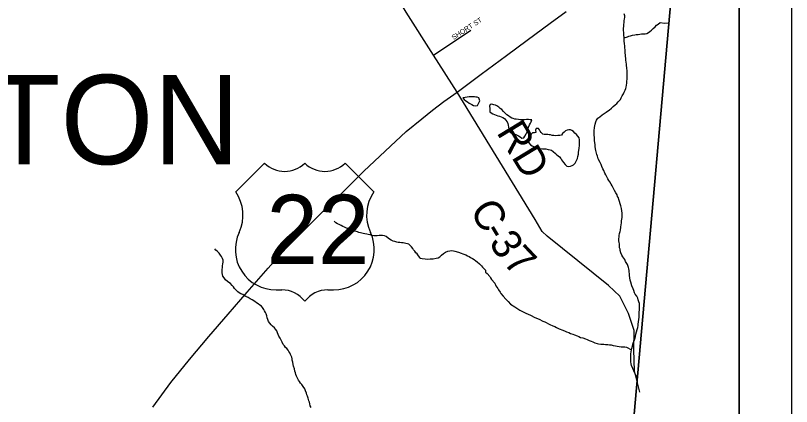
# Model space of a CAD drawing. Extents: x 0.4 to 34.4, y -2.1 to 19.9.
# Drawn here: x 8.419 to 9.9, y 13.092 to 13.838 of the extents above; entities that cross this region are included whole.
import ezdxf

# ---------------------------------------------------------------- set-up
doc = ezdxf.new("R2010")
doc.units = 0
for name, color, linetype in [('GM_X_Adjacent_County', 7, 'Continuous'), ('GM_X_County', 7, 'Continuous'), ('GM_X_County_Road', 7, 'Continuous'), ('GM_X_County_Road_Text', 7, 'Continuous'), ('GM_X_Minor_Lake', 7, 'Continuous'), ('GM_X_Minor_River', 7, 'Continuous'), ('GM_X_Township', 7, 'Continuous'), ('GM_X_Township_Subdivision', 7, 'Continuous'), ('GM_X_Township_Subdivision_Text', 7, 'Continuous'), ('GM_X_Township_Text', 7, 'Continuous'), ('GM_X_US_Route', 7, 'Continuous'), ('GM_X_US_Shield', 7, 'Continuous'), ('SH_Data', 7, 'Continuous')]:
    doc.layers.add(name, color=color, linetype=linetype)

msp = doc.modelspace()

# ---------------------------------------------------------------- linework, layer by layer
at = {"layer": 'GM_X_Adjacent_County'}
for points in [[(9.5074, 12.0357), (9.8001, 12.0357), (9.8001, 15.3423)], [(9.8001, 15.3423), (9.7654, 14.9495), (9.706, 14.2776), (9.6797, 13.9803), (9.6042, 13.1277), (9.5589, 12.6168), (9.5074, 12.0357)]]:
    msp.add_lwpolyline(points, dxfattribs=at)
at = {"layer": 'GM_X_County'}
msp.add_lwpolyline([(9.5074, 12.0357), (9.5589, 12.6168), (9.6042, 13.1277), (9.6797, 13.9803), (9.706, 14.2776), (9.7654, 14.9495), (9.8001, 15.3423)], dxfattribs=at)
at = {"layer": 'GM_X_County_Road'}
for points in [[(9.2621, 13.6921), (9.2169, 13.7627), (9.1648, 13.8442), (8.4596, 15.0199)], [(9.6108, 13.1195), (9.6004, 13.1602), (9.5991, 13.2001), (9.5997, 13.2369), (9.5888, 13.2697), (9.5727, 13.303), (9.5506, 13.323), (9.4339, 13.417), (9.4242, 13.4259), (9.4105, 13.4489), (9.2621, 13.6921)]]:
    msp.add_lwpolyline(points, dxfattribs=at)
at = {"layer": 'GM_X_Minor_Lake'}
for p, q in [((9.4043, 13.6389), (9.4013, 13.639)), ((9.417, 13.6228), (9.4124, 13.6225))]:
    msp.add_line(p, q, dxfattribs=at)
for points in [[(9.3033, 13.6717), (9.3038, 13.673), (9.305, 13.6756), (9.3032, 13.6813), (9.3001, 13.6825), (9.2975, 13.6826), (9.2948, 13.683), (9.291, 13.683), (9.288, 13.6831), (9.285, 13.6827), (9.2812, 13.6824), (9.2773, 13.6817), (9.2726, 13.6812)], [(9.2726, 13.6812), (9.275, 13.6779), (9.2784, 13.6756), (9.2814, 13.6733), (9.2848, 13.671), (9.2874, 13.6694), (9.2901, 13.6682), (9.2931, 13.6667), (9.2969, 13.6655), (9.3007, 13.6666), (9.3026, 13.67), (9.3033, 13.6717)], [(9.4013, 13.639), (9.3979, 13.6398), (9.3945, 13.6398), (9.3907, 13.6391), (9.3876, 13.6392), (9.385, 13.6392), (9.3823, 13.6392), (9.3789, 13.6397), (9.3747, 13.6401), (9.3721, 13.6405), (9.369, 13.6413), (9.366, 13.6425), (9.363, 13.6441), (9.3596, 13.6464), (9.357, 13.6483), (9.3536, 13.6518), (9.3506, 13.6552), (9.3469, 13.6587), (9.3443, 13.661), (9.3416, 13.6633), (9.3379, 13.6657), (9.3352, 13.6668), (9.3318, 13.668), (9.3281, 13.6692), (9.3246, 13.6681), (9.3238, 13.6651), (9.3241, 13.6605), (9.3244, 13.6541), (9.3271, 13.6522), (9.3301, 13.6506), (9.3331, 13.6494), (9.3365, 13.6482), (9.3395, 13.647), (9.3429, 13.6459), (9.3459, 13.6451), (9.349, 13.6435), (9.352, 13.6419), (9.3542, 13.6389), (9.3576, 13.635), (9.3587, 13.6323), (9.359, 13.6289), (9.3597, 13.6251), (9.3604, 13.6221), (9.3615, 13.6186), (9.3634, 13.6152), (9.3671, 13.6136), (9.3705, 13.6121), (9.3736, 13.6113), (9.3766, 13.6097), (9.3792, 13.6085), (9.3822, 13.6066), (9.3852, 13.6043), (9.389, 13.605), (9.391, 13.608), (9.3937, 13.6121), (9.3953, 13.6159), (9.3961, 13.6185), (9.3973, 13.6219), (9.3984, 13.6249), (9.4, 13.6295), (9.4016, 13.6325), (9.4031, 13.6351), (9.4043, 13.6389)], [(9.4124, 13.6225), (9.4116, 13.6191), (9.412, 13.6149), (9.4093, 13.6142), (9.4059, 13.6142), (9.4032, 13.612), (9.4012, 13.609), (9.3993, 13.6056), (9.3985, 13.6029), (9.3981, 13.5991), (9.3988, 13.5949), (9.4017, 13.5911), (9.4048, 13.5892), (9.4074, 13.5884), (9.41, 13.5868), (9.4134, 13.5856), (9.4176, 13.5844), (9.4206, 13.5844), (9.4248, 13.584), (9.4275, 13.5839), (9.4309, 13.5835), (9.4358, 13.5827), (9.4392, 13.5819), (9.4419, 13.5811), (9.4452, 13.5787), (9.4494, 13.5749), (9.452, 13.5726), (9.4546, 13.5706), (9.4572, 13.5683), (9.4595, 13.5656), (9.4613, 13.5629), (9.4651, 13.5579), (9.4681, 13.5537), (9.4714, 13.551), (9.4745, 13.5498), (9.4783, 13.5505), (9.4813, 13.552), (9.484, 13.5531), (9.4871, 13.5561), (9.4886, 13.5588), (9.4902, 13.5625), (9.4914, 13.5656), (9.4922, 13.5693), (9.4934, 13.5735), (9.4934, 13.5769), (9.4947, 13.5849), (9.4955, 13.5902), (9.4956, 13.5928), (9.4956, 13.5978), (9.4953, 13.6012), (9.4946, 13.605), (9.4924, 13.6081), (9.4894, 13.6111), (9.4864, 13.6138), (9.4838, 13.6169), (9.4811, 13.6185), (9.4781, 13.6197), (9.4751, 13.6201), (9.4716, 13.6194), (9.469, 13.6183), (9.4659, 13.6153), (9.4632, 13.6127), (9.4612, 13.6096), (9.4578, 13.6089), (9.454, 13.609), (9.4502, 13.6087), (9.4464, 13.6091), (9.4434, 13.6095), (9.44, 13.6103), (9.4373, 13.6107), (9.4347, 13.6112), (9.4317, 13.6112), (9.4282, 13.6112), (9.4256, 13.6117), (9.4222, 13.6147), (9.4203, 13.6174), (9.4189, 13.6201), (9.417, 13.6228)]]:
    msp.add_lwpolyline(points, dxfattribs=at)
at = {"layer": 'GM_X_Minor_River'}
for points in [[(9.5401, 13.5459), (9.5379, 13.5501), (9.5368, 13.5539), (9.5349, 13.5577), (9.5312, 13.5646), (9.5298, 13.5696), (9.5283, 13.573), (9.5265, 13.5806), (9.5255, 13.5875), (9.5252, 13.5913), (9.5245, 13.5958), (9.5241, 13.5989), (9.5242, 13.6023), (9.5238, 13.6057), (9.5235, 13.6095), (9.5236, 13.6141), (9.5236, 13.6183), (9.5241, 13.6243), (9.5253, 13.6308), (9.5265, 13.6353), (9.5281, 13.6387), (9.5304, 13.6421), (9.5343, 13.6451), (9.5385, 13.6484), (9.5427, 13.6514), (9.5462, 13.6536), (9.5489, 13.6555), (9.5519, 13.6573), (9.5565, 13.6611), (9.56, 13.6645), (9.5635, 13.6678), (9.5669, 13.6701), (9.5692, 13.6731), (9.5735, 13.6776), (9.575, 13.6809), (9.577, 13.6847), (9.5797, 13.6885), (9.5809, 13.6919), (9.5825, 13.6957), (9.5836, 13.6987), (9.5844, 13.7017), (9.5853, 13.7055), (9.5857, 13.7089), (9.5861, 13.7131), (9.5862, 13.7169), (9.5866, 13.7222), (9.5867, 13.7252), (9.5863, 13.7283), (9.5864, 13.7317), (9.5857, 13.7385), (9.5854, 13.7427), (9.5851, 13.7454), (9.5844, 13.7492), (9.5836, 13.753), (9.5837, 13.7564), (9.5834, 13.7598), (9.583, 13.7632), (9.5827, 13.7663), (9.5824, 13.7724), (9.5821, 13.7762), (9.5818, 13.78), (9.5814, 13.7838), (9.5808, 13.7898), (9.5804, 13.7952), (9.5802, 13.8012), (9.5798, 13.805), (9.5795, 13.81), (9.5796, 13.8138), (9.58, 13.8172), (9.5801, 13.8206), (9.5805, 13.8252), (9.5809, 13.8282), (9.5814, 13.832), (9.5818, 13.8346), (9.5818, 13.8377), (9.5807, 13.8415)], [(9.5804, 13.7952), (9.5869, 13.7977), (9.5896, 13.7988), (9.5927, 13.7996), (9.5969, 13.8006), (9.601, 13.8013), (9.6037, 13.8017), (9.6075, 13.802), (9.6106, 13.8027), (9.614, 13.803), (9.6174, 13.803), (9.6208, 13.8033), (9.6239, 13.804), (9.6273, 13.8059), (9.63, 13.8078), (9.6331, 13.8104), (9.6361, 13.813), (9.64, 13.8167), (9.6427, 13.8197), (9.6458, 13.8216), (9.6492, 13.8246), (9.6575, 13.8236), (9.6665, 13.8242)], [(9.6062, 13.1446), (9.5948, 13.1704), (9.594, 13.1738), (9.5937, 13.1772), (9.5934, 13.181), (9.5934, 13.1852), (9.5935, 13.1897), (9.5935, 13.1924), (9.594, 13.1962), (9.5948, 13.2), (9.5952, 13.2026), (9.5964, 13.2075), (9.5972, 13.2109), (9.598, 13.2136), (9.5996, 13.2174), (9.6008, 13.2215), (9.6024, 13.2257), (9.6032, 13.2299), (9.6044, 13.2344), (9.6056, 13.2389), (9.6068, 13.2431), (9.6072, 13.2465), (9.6076, 13.2495), (9.6081, 13.2537), (9.6089, 13.2582), (9.6094, 13.2628), (9.6094, 13.2658), (9.6095, 13.2696), (9.6095, 13.273), (9.6099, 13.2757), (9.61, 13.2791), (9.61, 13.2825), (9.6101, 13.2852), (9.6097, 13.289), (9.609, 13.292), (9.6075, 13.2959), (9.6065, 13.2989), (9.6046, 13.3027), (9.602, 13.3066), (9.6005, 13.3092), (9.5991, 13.3134), (9.5976, 13.3165), (9.5954, 13.3226), (9.5936, 13.3291), (9.5921, 13.3333), (9.5918, 13.3378), (9.5911, 13.3424), (9.5908, 13.3451), (9.5905, 13.3489), (9.5905, 13.3515), (9.5898, 13.355), (9.5891, 13.3576), (9.5872, 13.3633), (9.5835, 13.3691), (9.5817, 13.3725), (9.578, 13.3779), (9.5765, 13.381), (9.5746, 13.3852), (9.5732, 13.3897), (9.5728, 13.3924), (9.5721, 13.3951), (9.5715, 13.4027), (9.5711, 13.4053), (9.5708, 13.4084), (9.5705, 13.4126), (9.5709, 13.4152), (9.5713, 13.4186), (9.5717, 13.422), (9.5729, 13.4258), (9.5734, 13.4285), (9.5742, 13.4342), (9.575, 13.4391), (9.5754, 13.4421), (9.5759, 13.4463), (9.5763, 13.4497), (9.5767, 13.4527), (9.5768, 13.4577), (9.5769, 13.4611), (9.5762, 13.4653), (9.5755, 13.4698), (9.5747, 13.4725), (9.5744, 13.4752), (9.5733, 13.4786), (9.5719, 13.4835), (9.5704, 13.4874), (9.5697, 13.49), (9.5682, 13.4931), (9.5671, 13.4958), (9.5649, 13.5), (9.5623, 13.5042), (9.5597, 13.5092), (9.5578, 13.513), (9.556, 13.5164), (9.5534, 13.5206), (9.5515, 13.5233), (9.5497, 13.5268), (9.5475, 13.5306), (9.5456, 13.5344), (9.5438, 13.5375), (9.5416, 13.5424), (9.5401, 13.5459)], [(9.191, 13.3751), (9.1855, 13.3836), (9.1829, 13.3856), (9.1811, 13.3883), (9.1785, 13.391), (9.177, 13.3937), (9.1748, 13.3971), (9.1722, 13.3995), (9.1695, 13.4018), (9.1669, 13.4026), (9.1642, 13.4034), (9.1616, 13.4038), (9.1589, 13.4043), (9.1555, 13.4047), (9.1525, 13.4048), (9.1494, 13.4052), (9.1468, 13.4056), (9.1426, 13.4069), (9.1396, 13.4077), (9.1362, 13.4093), (9.1328, 13.4112), (9.1302, 13.4136), (9.1264, 13.4163), (9.123, 13.4179), (9.1196, 13.4183), (9.1162, 13.4184), (9.1127, 13.4184), (9.1093, 13.4181), (9.1062, 13.4178), (9.1028, 13.4179), (9.0994, 13.4187), (9.0956, 13.4195), (9.0918, 13.4203), (9.0892, 13.4212), (9.0857, 13.4216), (9.0827, 13.422), (9.08, 13.4228), (9.0774, 13.4233), (9.0744, 13.4241), (9.0717, 13.4253), (9.0668, 13.4265), (9.0634, 13.4285), (9.0607, 13.4293), (9.057, 13.4305), (9.0536, 13.4317), (9.0509, 13.4325), (9.0471, 13.4341), (9.0437, 13.4353), (9.0403, 13.4373), (9.0369, 13.4392), (9.0336, 13.4408), (9.0302, 13.4428), (9.0268, 13.4455)], [(8.8852, 13.2856), (8.8822, 13.288), (8.8788, 13.2899), (8.8758, 13.2927), (8.8705, 13.2954), (8.8668, 13.2978), (8.8626, 13.3001), (8.8585, 13.3021), (8.8551, 13.3041), (8.8525, 13.3056), (8.8491, 13.3072), (8.8457, 13.3092), (8.8431, 13.3111), (8.8397, 13.3143), (8.8371, 13.3173), (8.8349, 13.3204), (8.8323, 13.3231), (8.8289, 13.327), (8.8263, 13.329), (8.8233, 13.3305), (8.8195, 13.334), (8.817, 13.3379), (8.8147, 13.341), (8.8137, 13.344), (8.8134, 13.3475), (8.8134, 13.3509), (8.8131, 13.3543), (8.8136, 13.357), (8.814, 13.3608), (8.8145, 13.3642), (8.815, 13.3676), (8.8151, 13.3714), (8.814, 13.3748), (8.8122, 13.3783), (8.8103, 13.381), (8.8073, 13.3845), (8.8044, 13.3879), (8.8014, 13.3903), (8.7991, 13.393)], [(9.191, 13.3751), (9.1951, 13.3745), (9.2008, 13.3737), (9.205, 13.3733), (9.2103, 13.3736), (9.216, 13.3739), (9.2217, 13.3749), (9.2259, 13.376), (9.2286, 13.3775), (9.2317, 13.3812), (9.2355, 13.3842), (9.2398, 13.3868), (9.244, 13.3887), (9.2478, 13.3894), (9.2519, 13.3897), (9.2546, 13.3893), (9.2576, 13.3885), (9.2644, 13.3869), (9.2693, 13.3849), (9.2727, 13.3833), (9.2784, 13.3813), (9.2814, 13.3798), (9.2848, 13.3786), (9.2875, 13.3767), (9.2912, 13.3747), (9.2946, 13.3724), (9.2976, 13.3704), (9.3002, 13.3685), (9.3047, 13.3643), (9.3081, 13.3608), (9.3104, 13.3581), (9.3133, 13.355), (9.316, 13.352), (9.3163, 13.3485), (9.3193, 13.3458), (9.3241, 13.3405), (9.3256, 13.3378), (9.3275, 13.3347), (9.3335, 13.3278), (9.336, 13.3221), (9.3394, 13.3175), (9.3405, 13.3148), (9.3438, 13.3102), (9.3453, 13.3075), (9.3498, 13.3025), (9.3547, 13.2971), (9.3592, 13.2925), (9.364, 13.2875), (9.3719, 13.2821), (9.3817, 13.2762), (9.3844, 13.2747), (9.393, 13.2704), (9.4021, 13.2665), (9.4104, 13.2622), (9.4183, 13.259), (9.4255, 13.2551), (9.4292, 13.2536), (9.4319, 13.2524), (9.4364, 13.25), (9.439, 13.2489), (9.4443, 13.2461), (9.4481, 13.2446), (9.4515, 13.243), (9.4541, 13.2418), (9.4568, 13.2406), (9.4636, 13.2379), (9.4681, 13.2359), (9.4707, 13.2347), (9.4753, 13.2332), (9.4783, 13.2316), (9.4824, 13.23), (9.4862, 13.2292), (9.4911, 13.2269), (9.4942, 13.2257), (9.4975, 13.2241), (9.5021, 13.2229), (9.5066, 13.2213), (9.51, 13.2201), (9.5138, 13.2182), (9.5176, 13.2166), (9.5206, 13.2154), (9.5247, 13.2135), (9.5293, 13.2127), (9.5319, 13.2119), (9.5361, 13.2114), (9.5418, 13.211), (9.5448, 13.2105), (9.5494, 13.2105), (9.5524, 13.2101), (9.5562, 13.21), (9.5596, 13.2088), (9.5642, 13.208), (9.5672, 13.2076), (9.571, 13.2068), (9.5748, 13.2063), (9.5786, 13.2063), (9.582, 13.2058), (9.585, 13.2054), (9.5948, 13.2)], [(8.9829, 13.0902), (8.9815, 13.0937), (8.9804, 13.0971), (8.9797, 13.1002), (8.979, 13.1028), (8.9783, 13.1055), (8.9776, 13.1082), (8.9762, 13.112), (8.9751, 13.1147), (8.9744, 13.1178), (8.9726, 13.122), (8.9708, 13.1262), (8.9678, 13.1304), (8.9656, 13.1339), (8.963, 13.137), (8.9608, 13.1397), (8.9593, 13.1424), (8.9575, 13.1451), (8.9564, 13.1478), (8.9553, 13.1504), (8.9539, 13.1531), (8.9532, 13.1566), (8.9521, 13.1596), (8.9511, 13.1638), (8.9497, 13.1692), (8.949, 13.1726), (8.9483, 13.1768), (8.9472, 13.1803), (8.9469, 13.1829), (8.9462, 13.1864), (8.9448, 13.1891), (8.9437, 13.1917), (8.9426, 13.1944), (8.9404, 13.1971), (8.9393, 13.1998), (8.9367, 13.2029), (8.9341, 13.2049), (8.9322, 13.2079), (8.93, 13.2106), (8.9278, 13.2149), (8.9252, 13.2199), (8.9238, 13.2225), (8.9216, 13.2264), (8.9205, 13.2295), (8.9191, 13.2325), (8.9176, 13.2364), (8.9154, 13.2398), (8.9132, 13.2425), (8.9094, 13.2456), (8.9068, 13.2483), (8.9042, 13.2511), (8.902, 13.2545), (8.9002, 13.258), (8.8995, 13.2614), (8.8984, 13.2649), (8.897, 13.2687), (8.8959, 13.2714), (8.8941, 13.2748), (8.893, 13.2775), (8.8904, 13.281), (8.8882, 13.2837), (8.8852, 13.2856)]]:
    msp.add_lwpolyline(points, dxfattribs=at)
at = {"layer": 'GM_X_Township'}
msp.add_lwpolyline([(9.5074, 12.0357), (9.5589, 12.6168), (9.6042, 13.1277), (9.6797, 13.9803), (9.706, 14.2776), (9.7654, 14.9495), (9.8001, 15.3423)], dxfattribs=at)
at = {"layer": 'GM_X_Township_Subdivision'}
msp.add_lwpolyline([(9.2169, 13.7627), (9.2877, 13.8101)], dxfattribs=at)
at = {"layer": 'GM_X_US_Route'}
msp.add_lwpolyline([(8.681, 13.0911), (8.7156, 13.1377), (8.7512, 13.182), (8.7876, 13.226), (8.8248, 13.2684), (8.8608, 13.3101), (8.901, 13.3559), (8.9347, 13.3935), (8.9695, 13.428), (9.0043, 13.4629), (9.0433, 13.5007), (9.0835, 13.5409), (9.1244, 13.5795), (9.1645, 13.6166), (9.1942, 13.6411), (9.2147, 13.6576), (9.2366, 13.6738), (9.2621, 13.6921), (9.3079, 13.7259), (9.3561, 13.7615), (9.3958, 13.7909), (9.4397, 13.8232), (9.4698, 13.8456)], dxfattribs=at)
at = {"layer": 'GM_X_US_Shield'}
for p, q in [((8.8941, 13.5565), (8.8392, 13.5016)), ((9.1029, 13.5016), (9.0479, 13.5565)), ((8.9161, 13.3148), (8.9271, 13.3148)), ((9.015, 13.3148), (9.026, 13.3148))]:
    msp.add_line(p, q, dxfattribs=at)
for centre, radius, start, end in [((8.9326, 13.5957), 0.0549, 225.573, 314.427), ((9.0095, 13.5957), 0.0549, 225.573, 314.427), ((8.7762, 13.4575), 0.0769, 334.5471, 35.0009), ((9.1659, 13.4575), 0.0769, 144.9991, 205.4529), ((8.9153, 13.3917), 0.0769, 154.8319, 270.6383), ((9.0268, 13.3917), 0.0769, 269.3617, 25.1681), ((8.9271, 13.2599), 0.0549, 36.8699, 90), ((9.015, 13.2599), 0.0549, 90, 143.1301)]:
    msp.add_arc(centre, radius, start, end, dxfattribs=at)
at = {"layer": 'SH_Data'}
for p, q in [((9.9001, 18.9357), (9.9001, 11.9357)), ((9.8001, 18.8357), (9.8001, 12.0357))]:
    msp.add_line(p, q, dxfattribs=at)

# ---------------------------------------------------------------- texts
at = {"layer": 'GM_X_County_Road_Text'}
for s, height, rotation, p in [('RD', 0.05682, 301.2192, (9.336, 13.6154)), ('C', 0.0568, 301.0186, (9.2847, 13.4665)), ('-', 0.0568, 301.2226, (9.3088, 13.4263)), ('3', 0.0568, 302.1036, (9.3214, 13.4055)), ('7', 0.0568, 313.3261, (9.3474, 13.3663))]:
    msp.add_text(s, height=height, rotation=rotation, dxfattribs=at).set_placement(p)
at = {"layer": 'GM_X_Township_Subdivision_Text'}
msp.add_text('SHORT ST', height=0.00947, rotation=32.9505, dxfattribs=at).set_placement((9.2551, 13.7911))
at = {"layer": 'GM_X_Township_Text'}
msp.add_text('WASHINGTON', height=0.17045, rotation=0, dxfattribs=at).set_placement((7.2765, 13.5544))
at = {"layer": 'GM_X_US_Shield'}
msp.add_text('22', height=0.13184, dxfattribs=at).set_placement((8.8981, 13.3642))

doc.saveas('drawing.dxf')
